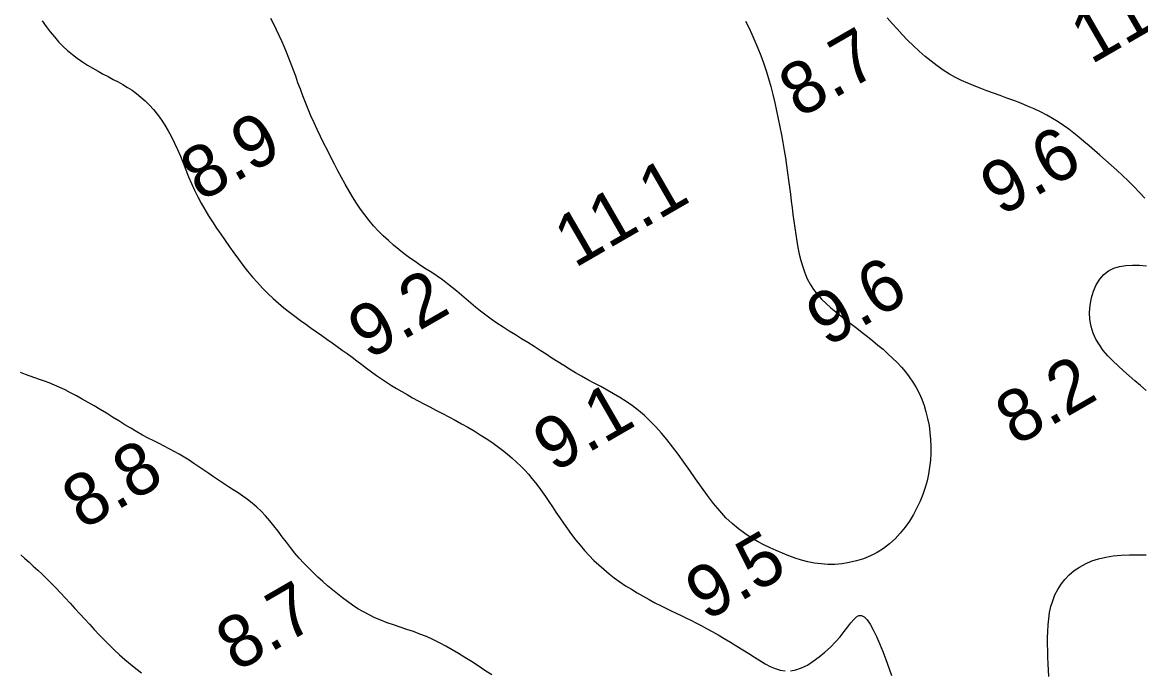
# Model space of a CAD drawing. Extents: x 3024098 to 3056816, y 418252 to 509144.
# Drawn here: x 3036054 to 3036161.3, y 419851.5 to 419913.7 of the extents above; entities that cross this region are included whole.
import ezdxf

# ---------------------------------------------------------------- set-up
doc = ezdxf.new("R2010")
doc.units = 0
doc.layers.add('V-CHAN-CONT-EL10', color=7, linetype='Continuous')
doc.layers.add('V-TOPO-SOUN-0911', color=7, linetype='Continuous')

msp = doc.modelspace()

# ---------------------------------------------------------------- linework, layer by layer
at = {"layer": 'V-CHAN-CONT-EL10'}
for points in [[(3036055.9, 419913.8), (3036056.29, 419913.27), (3036056.68, 419912.76), (3036057.08, 419912.27), (3036057.48, 419911.81), (3036057.9, 419911.37), (3036058.34, 419910.96), (3036058.81, 419910.58), (3036059.28, 419910.22), (3036059.77, 419909.88), (3036060.27, 419909.57), (3036060.77, 419909.27), (3036061.27, 419908.98), (3036061.77, 419908.71), (3036062.25, 419908.46), (3036062.73, 419908.2), (3036063.19, 419907.95), (3036063.65, 419907.7), (3036064.1, 419907.43), (3036064.53, 419907.15), (3036064.96, 419906.84), (3036065.38, 419906.5), (3036065.8, 419906.14), (3036066.2, 419905.73), (3036066.59, 419905.3), (3036066.97, 419904.84), (3036067.33, 419904.35), (3036067.68, 419903.82), (3036068.01, 419903.27), (3036068.33, 419902.69), (3036068.62, 419902.09), (3036068.9, 419901.47), (3036069.17, 419900.83), (3036069.43, 419900.18), (3036069.69, 419899.52), (3036069.96, 419898.86), (3036070.24, 419898.21), (3036070.53, 419897.57), (3036070.84, 419896.94), (3036071.17, 419896.32), (3036071.52, 419895.71), (3036071.88, 419895.11), (3036072.26, 419894.52), (3036072.65, 419893.93), (3036073.05, 419893.34), (3036073.46, 419892.74), (3036073.87, 419892.15), (3036074.29, 419891.55), (3036074.73, 419890.96), (3036075.17, 419890.38), (3036075.62, 419889.8), (3036076.08, 419889.24), (3036076.56, 419888.7), (3036077.05, 419888.17), (3036077.55, 419887.67), (3036078.06, 419887.19), (3036078.58, 419886.74), (3036079.1, 419886.3), (3036079.63, 419885.88), (3036080.16, 419885.48), (3036080.68, 419885.08), (3036081.21, 419884.71), (3036081.72, 419884.34), (3036082.23, 419883.98), (3036082.73, 419883.62), (3036083.23, 419883.28), (3036083.72, 419882.93), (3036084.21, 419882.59), (3036084.69, 419882.24), (3036085.17, 419881.9), (3036085.64, 419881.55), (3036086.11, 419881.2), (3036086.58, 419880.85), (3036087.04, 419880.5), (3036087.51, 419880.15), (3036087.98, 419879.81), (3036088.45, 419879.48), (3036088.93, 419879.16), (3036089.41, 419878.85), (3036089.9, 419878.55), (3036090.41, 419878.25), (3036090.92, 419877.96), (3036091.44, 419877.67), (3036091.98, 419877.38), (3036092.53, 419877.09), (3036093.1, 419876.79), (3036093.69, 419876.48), (3036094.3, 419876.16), (3036094.91, 419875.84), (3036095.52, 419875.51), (3036096.14, 419875.17), (3036096.75, 419874.83), (3036097.35, 419874.48), (3036097.93, 419874.12), (3036098.5, 419873.76), (3036099.04, 419873.4), (3036099.56, 419873.02), (3036100.06, 419872.65), (3036100.53, 419872.27), (3036100.99, 419871.88), (3036101.41, 419871.5), (3036101.82, 419871.11), (3036102.2, 419870.72), (3036102.56, 419870.32), (3036102.9, 419869.92), (3036103.23, 419869.51), (3036103.55, 419869.09), (3036103.87, 419868.65), (3036104.19, 419868.19), (3036104.52, 419867.71), (3036104.86, 419867.21), (3036105.2, 419866.69), (3036105.56, 419866.16), (3036105.93, 419865.62), (3036106.31, 419865.09), (3036106.7, 419864.55), (3036107.11, 419864.02), (3036107.52, 419863.51), (3036107.95, 419863.01), (3036108.39, 419862.53), (3036108.84, 419862.07), (3036109.31, 419861.63), (3036109.79, 419861.21), (3036110.29, 419860.79), (3036110.8, 419860.4), (3036111.33, 419860.01), (3036111.88, 419859.64), (3036112.44, 419859.29), (3036113, 419858.95), (3036113.57, 419858.62), (3036114.13, 419858.31), (3036114.69, 419858.01), (3036115.23, 419857.73), (3036115.75, 419857.47), (3036116.25, 419857.23), (3036116.73, 419857), (3036117.2, 419856.77), (3036117.67, 419856.55), (3036118.14, 419856.32), (3036118.62, 419856.08), (3036119.12, 419855.82), (3036119.64, 419855.54), (3036120.19, 419855.24), (3036120.76, 419854.91), (3036121.35, 419854.56), (3036121.94, 419854.21), (3036122.54, 419853.85), (3036123.13, 419853.48), (3036123.7, 419853.13), (3036124.25, 419852.78), (3036124.77, 419852.46), (3036125.27, 419852.16), (3036125.76, 419851.9), (3036126.24, 419851.69), (3036126.71, 419851.54), (3036127.2, 419851.46)], [(3036123.37, 419913.78), (3036123.69, 419913.16), (3036124, 419912.53), (3036124.29, 419911.87), (3036124.58, 419911.19), (3036124.86, 419910.49), (3036125.12, 419909.77), (3036125.36, 419909.03), (3036125.59, 419908.28), (3036125.8, 419907.51), (3036126, 419906.74), (3036126.19, 419905.96), (3036126.37, 419905.19), (3036126.53, 419904.41), (3036126.69, 419903.65), (3036126.83, 419902.89), (3036126.96, 419902.14), (3036127.09, 419901.39), (3036127.21, 419900.66), (3036127.32, 419899.94), (3036127.42, 419899.23), (3036127.52, 419898.54), (3036127.61, 419897.86), (3036127.7, 419897.19), (3036127.78, 419896.53), (3036127.86, 419895.89), (3036127.94, 419895.24), (3036128.03, 419894.6), (3036128.12, 419893.97), (3036128.21, 419893.33), (3036128.31, 419892.69), (3036128.42, 419892.06), (3036128.54, 419891.43), (3036128.69, 419890.81), (3036128.87, 419890.21), (3036129.07, 419889.63), (3036129.31, 419889.07), (3036129.59, 419888.54), (3036129.92, 419888.04), (3036130.28, 419887.57), (3036130.68, 419887.13), (3036131.12, 419886.7), (3036131.57, 419886.29), (3036132.05, 419885.89), (3036132.55, 419885.5), (3036133.05, 419885.11), (3036133.56, 419884.72), (3036134.07, 419884.33), (3036134.59, 419883.93), (3036135.1, 419883.53), (3036135.6, 419883.13), (3036136.09, 419882.72), (3036136.58, 419882.31), (3036137.05, 419881.89), (3036137.5, 419881.47), (3036137.93, 419881.04), (3036138.35, 419880.6), (3036138.74, 419880.14), (3036139.1, 419879.67), (3036139.44, 419879.17), (3036139.76, 419878.65), (3036140.04, 419878.11), (3036140.29, 419877.53), (3036140.51, 419876.93), (3036140.7, 419876.3), (3036140.86, 419875.66), (3036140.99, 419875.01), (3036141.08, 419874.34), (3036141.14, 419873.67), (3036141.17, 419873), (3036141.16, 419872.33), (3036141.12, 419871.67), (3036141.05, 419871.01), (3036140.94, 419870.35), (3036140.8, 419869.7), (3036140.61, 419869.04), (3036140.39, 419868.39), (3036140.13, 419867.74), (3036139.83, 419867.1), (3036139.49, 419866.46), (3036139.11, 419865.84), (3036138.69, 419865.24), (3036138.23, 419864.67), (3036137.73, 419864.13), (3036137.19, 419863.64), (3036136.62, 419863.2), (3036136.01, 419862.82), (3036135.37, 419862.49), (3036134.71, 419862.23), (3036134.03, 419862.01), (3036133.34, 419861.85), (3036132.65, 419861.74), (3036131.97, 419861.68), (3036131.29, 419861.67), (3036130.64, 419861.72), (3036130, 419861.8), (3036129.37, 419861.93), (3036128.75, 419862.1), (3036128.14, 419862.29), (3036127.54, 419862.51), (3036126.94, 419862.75), (3036126.34, 419863.01), (3036125.74, 419863.27), (3036125.13, 419863.56), (3036124.52, 419863.88), (3036123.92, 419864.23), (3036123.31, 419864.63), (3036122.71, 419865.08), (3036122.11, 419865.59), (3036121.51, 419866.16), (3036120.92, 419866.82), (3036120.33, 419867.53), (3036119.74, 419868.29), (3036119.17, 419869.08), (3036118.6, 419869.89), (3036118.03, 419870.7), (3036117.47, 419871.49), (3036116.92, 419872.25), (3036116.38, 419872.97), (3036115.84, 419873.65), (3036115.31, 419874.28), (3036114.77, 419874.88), (3036114.23, 419875.43), (3036113.68, 419875.95), (3036113.11, 419876.43), (3036112.54, 419876.88), (3036111.95, 419877.29), (3036111.34, 419877.68), (3036110.73, 419878.04), (3036110.11, 419878.39), (3036109.49, 419878.73), (3036108.87, 419879.06), (3036108.26, 419879.38), (3036107.66, 419879.72), (3036107.08, 419880.05), (3036106.5, 419880.4), (3036105.94, 419880.75), (3036105.38, 419881.11), (3036104.82, 419881.47), (3036104.25, 419881.84), (3036103.68, 419882.21), (3036103.1, 419882.58), (3036102.51, 419882.95), (3036101.91, 419883.32), (3036101.31, 419883.69), (3036100.71, 419884.06), (3036100.12, 419884.44), (3036099.54, 419884.82), (3036098.99, 419885.19), (3036098.46, 419885.58), (3036097.96, 419885.96), (3036097.48, 419886.34), (3036097.02, 419886.73), (3036096.58, 419887.11), (3036096.14, 419887.49), (3036095.7, 419887.87), (3036095.25, 419888.24), (3036094.78, 419888.6), (3036094.3, 419888.96), (3036093.8, 419889.31), (3036093.28, 419889.66), (3036092.76, 419890.01), (3036092.22, 419890.36), (3036091.69, 419890.72), (3036091.16, 419891.09), (3036090.63, 419891.47), (3036090.12, 419891.87), (3036089.61, 419892.29), (3036089.12, 419892.73), (3036088.63, 419893.18), (3036088.16, 419893.65), (3036087.71, 419894.14), (3036087.27, 419894.66), (3036086.85, 419895.19), (3036086.45, 419895.75), (3036086.06, 419896.32), (3036085.69, 419896.92), (3036085.32, 419897.53), (3036084.97, 419898.15), (3036084.62, 419898.79), (3036084.28, 419899.43), (3036083.94, 419900.08), (3036083.6, 419900.74), (3036083.27, 419901.4), (3036082.94, 419902.05), (3036082.61, 419902.72), (3036082.29, 419903.38), (3036081.99, 419904.04), (3036081.69, 419904.69), (3036081.42, 419905.34), (3036081.16, 419905.99), (3036080.91, 419906.63), (3036080.68, 419907.26), (3036080.45, 419907.88), (3036080.23, 419908.49), (3036080.02, 419909.09), (3036079.8, 419909.67), (3036079.58, 419910.24), (3036079.36, 419910.79), (3036079.13, 419911.34), (3036078.9, 419911.87), (3036078.65, 419912.4), (3036078.39, 419912.94), (3036078.12, 419913.48), (3036077.84, 419914.04)], [(3036161.71, 419896.8), (3036161.18, 419897.36), (3036160.64, 419897.92), (3036160.1, 419898.45), (3036159.55, 419898.98), (3036159, 419899.49), (3036158.46, 419899.98), (3036157.92, 419900.46), (3036157.39, 419900.93), (3036156.86, 419901.38), (3036156.35, 419901.82), (3036155.85, 419902.24), (3036155.36, 419902.64), (3036154.88, 419903.03), (3036154.39, 419903.41), (3036153.89, 419903.77), (3036153.38, 419904.11), (3036152.84, 419904.45), (3036152.28, 419904.76), (3036151.69, 419905.07), (3036151.08, 419905.36), (3036150.44, 419905.63), (3036149.79, 419905.9), (3036149.13, 419906.16), (3036148.47, 419906.4), (3036147.81, 419906.64), (3036147.17, 419906.88), (3036146.53, 419907.1), (3036145.91, 419907.34), (3036145.31, 419907.57), (3036144.71, 419907.82), (3036144.12, 419908.09), (3036143.53, 419908.39), (3036142.94, 419908.71), (3036142.36, 419909.08), (3036141.77, 419909.48), (3036141.19, 419909.93), (3036140.62, 419910.4), (3036140.04, 419910.9), (3036139.49, 419911.42), (3036138.94, 419911.96), (3036138.42, 419912.49), (3036137.92, 419913.03), (3036137.44, 419913.57), (3036136.99, 419914.09)], [(3036161.83, 419878.37), (3036161.27, 419878.83), (3036160.72, 419879.29), (3036160.18, 419879.76), (3036159.65, 419880.24), (3036159.13, 419880.71), (3036158.62, 419881.2), (3036158.15, 419881.69), (3036157.71, 419882.2), (3036157.33, 419882.73), (3036156.99, 419883.28), (3036156.73, 419883.87), (3036156.54, 419884.5), (3036156.43, 419885.16), (3036156.4, 419885.85), (3036156.45, 419886.55), (3036156.57, 419887.23), (3036156.77, 419887.88), (3036157.04, 419888.49), (3036157.37, 419889.02), (3036157.77, 419889.47), (3036158.22, 419889.82), (3036158.73, 419890.08), (3036159.28, 419890.26), (3036159.88, 419890.36), (3036160.52, 419890.39), (3036161.18, 419890.38), (3036161.87, 419890.32)], [(3036099.04, 419851.08), (3036098.38, 419851.52), (3036097.73, 419851.95), (3036097.1, 419852.36), (3036096.47, 419852.76), (3036095.85, 419853.14), (3036095.24, 419853.5), (3036094.63, 419853.85), (3036094.02, 419854.17), (3036093.4, 419854.47), (3036092.78, 419854.75), (3036092.15, 419855), (3036091.52, 419855.23), (3036090.89, 419855.45), (3036090.25, 419855.66), (3036089.63, 419855.87), (3036089.01, 419856.09), (3036088.41, 419856.32), (3036087.83, 419856.56), (3036087.27, 419856.83), (3036086.73, 419857.12), (3036086.2, 419857.43), (3036085.69, 419857.76), (3036085.19, 419858.11), (3036084.71, 419858.47), (3036084.23, 419858.85), (3036083.75, 419859.23), (3036083.28, 419859.63), (3036082.82, 419860.04), (3036082.35, 419860.46), (3036081.9, 419860.89), (3036081.45, 419861.34), (3036081.01, 419861.8), (3036080.58, 419862.28), (3036080.15, 419862.77), (3036079.74, 419863.29), (3036079.34, 419863.81), (3036078.94, 419864.34), (3036078.54, 419864.86), (3036078.15, 419865.37), (3036077.75, 419865.87), (3036077.34, 419866.34), (3036076.93, 419866.78), (3036076.5, 419867.18), (3036076.06, 419867.55), (3036075.62, 419867.9), (3036075.17, 419868.22), (3036074.71, 419868.53), (3036074.24, 419868.83), (3036073.77, 419869.13), (3036073.3, 419869.44), (3036072.83, 419869.75), (3036072.36, 419870.08), (3036071.89, 419870.4), (3036071.42, 419870.73), (3036070.94, 419871.05), (3036070.47, 419871.37), (3036070, 419871.67), (3036069.52, 419871.97), (3036069.05, 419872.24), (3036068.58, 419872.5), (3036068.1, 419872.75), (3036067.61, 419873.01), (3036067.12, 419873.26), (3036066.61, 419873.52), (3036066.09, 419873.79), (3036065.55, 419874.09), (3036065, 419874.4), (3036064.43, 419874.73), (3036063.85, 419875.08), (3036063.26, 419875.44), (3036062.66, 419875.8), (3036062.07, 419876.17), (3036061.48, 419876.53), (3036060.89, 419876.88), (3036060.31, 419877.22), (3036059.74, 419877.54), (3036059.19, 419877.85), (3036058.64, 419878.14), (3036058.11, 419878.41), (3036057.59, 419878.66), (3036057.08, 419878.88), (3036056.59, 419879.09), (3036056.12, 419879.26), (3036055.66, 419879.42), (3036055.2, 419879.58), (3036054.75, 419879.74), (3036054.3, 419879.9), (3036053.83, 419880.09)], [(3036053.86, 419862.61), (3036054.25, 419862.25), (3036054.65, 419861.89), (3036055.06, 419861.52), (3036055.48, 419861.14), (3036055.9, 419860.74), (3036056.33, 419860.33), (3036056.77, 419859.89), (3036057.22, 419859.43), (3036057.67, 419858.96), (3036058.12, 419858.47), (3036058.58, 419857.97), (3036059.05, 419857.46), (3036059.51, 419856.95), (3036059.98, 419856.45), (3036060.44, 419855.94), (3036060.91, 419855.44), (3036061.38, 419854.94), (3036061.85, 419854.45), (3036062.33, 419853.97), (3036062.83, 419853.49), (3036063.33, 419853.02), (3036063.84, 419852.57), (3036064.37, 419852.12), (3036064.9, 419851.69), (3036065.45, 419851.27)], [(3036152.48, 419850.93), (3036152.46, 419851.54), (3036152.43, 419852.15), (3036152.4, 419852.77), (3036152.39, 419853.39), (3036152.37, 419854.02), (3036152.37, 419854.64), (3036152.38, 419855.26), (3036152.42, 419855.87), (3036152.47, 419856.47), (3036152.56, 419857.06), (3036152.69, 419857.64), (3036152.86, 419858.2), (3036153.07, 419858.75), (3036153.34, 419859.27), (3036153.66, 419859.77), (3036154.03, 419860.24), (3036154.45, 419860.68), (3036154.92, 419861.08), (3036155.44, 419861.43), (3036156, 419861.75), (3036156.61, 419862.01), (3036157.26, 419862.21), (3036157.95, 419862.37), (3036158.67, 419862.49), (3036159.43, 419862.56), (3036160.21, 419862.6), (3036161.01, 419862.61), (3036161.83, 419862.6)], [(3036127.7, 419851.46), (3036128.22, 419851.56), (3036128.76, 419851.75), (3036129.32, 419852.03), (3036129.89, 419852.39), (3036130.46, 419852.8), (3036131.01, 419853.26), (3036131.54, 419853.74), (3036132.03, 419854.24), (3036132.47, 419854.74), (3036132.86, 419855.23), (3036133.2, 419855.68), (3036133.5, 419856.07), (3036133.77, 419856.4), (3036134.02, 419856.64), (3036134.27, 419856.78), (3036134.52, 419856.79), (3036134.77, 419856.66), (3036135.05, 419856.37), (3036135.34, 419855.95), (3036135.64, 419855.41), (3036135.94, 419854.78), (3036136.25, 419854.08), (3036136.56, 419853.33), (3036136.85, 419852.55), (3036137.14, 419851.77), (3036137.4, 419851.01)]]:
    msp.add_lwpolyline(points, dxfattribs=at)

# ---------------------------------------------------------------- texts
at = {"layer": 'V-TOPO-SOUN-0911'}
for s, p in [('11.0 ', (3036156.53, 419909.58)), ('8.7', (3036128.56, 419904.41)), ('8.9', (3036071.14, 419896.4)), ('9.6', (3036147.88, 419895)), ('11.1 ', (3036106.99, 419890.05)), ('9.6', (3036131.18, 419882.46)), ('9.2', (3036087.22, 419881.25)), ('8.2', (3036149.33, 419872.98)), ('9.1', (3036104.98, 419870.43)), ('8.8', (3036059.79, 419864.94)), ('9.5', (3036119.59, 419856.18)), ('8.7', (3036074.56, 419851.32))]:
    msp.add_text(s, height=5, rotation=30, dxfattribs=at).set_placement(p)

doc.saveas('drawing.dxf')
